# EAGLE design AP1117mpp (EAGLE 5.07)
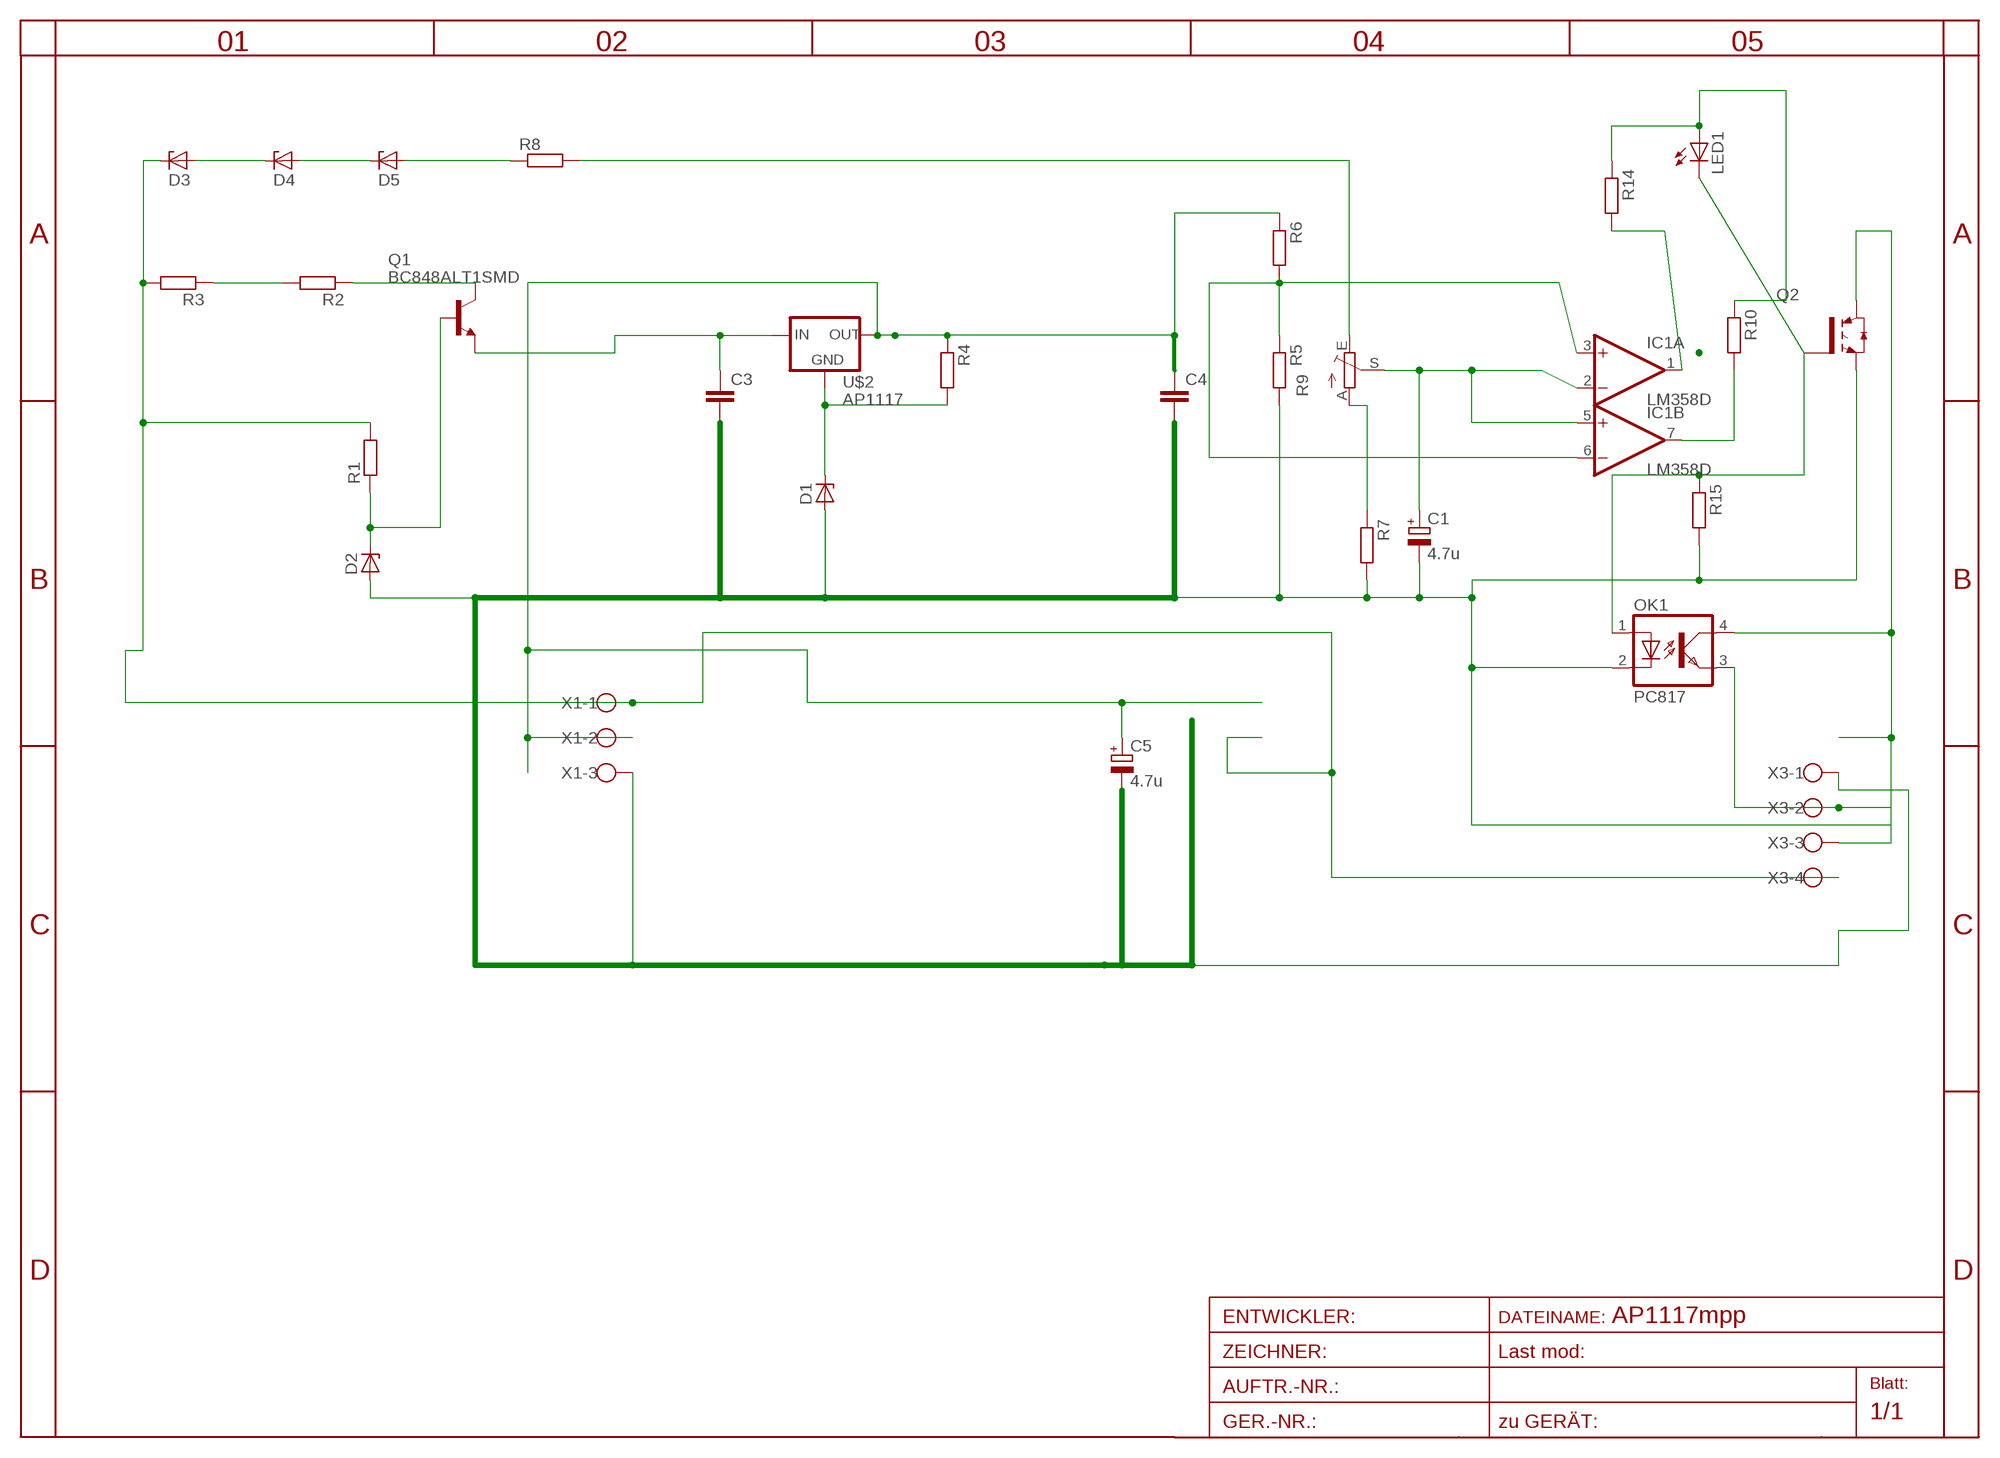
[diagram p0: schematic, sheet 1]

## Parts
C1  4.7u  CPOL-EUSANYO_SMD_C6  [SANYO-OSCON_SMD_C6]
C3  C-EUC1206  [C1206]
C4  C-EUC1206  [C1206]
C5  4.7u  CPOL-EUSANYO_SMD_C6  [SANYO-OSCON_SMD_C6]
D1  ZENER-DIODESOD80C  [SOD80C]
D2  ZENER-DIODESOD80C  [SOD80C]
D3  ZENER-DIODESOD80C  [SOD80C]
D4  ZENER-DIODESOD80C  [SOD80C]
D5  ZENER-DIODESOD80C  [SOD80C]
IC1  LM358D  [SO08]
LED1  LEDCHIPLED_1206  [CHIPLED_1206]
OK1  PC817  [DIL04]
Q1  BC848ALT1SMD  [SOT23]
Q2  IRG4BC15UD-S  [D2PACK]
R1  R-EU_R1206  [R1206]
R2  R-EU_R1206  [R1206]
R3  R-EU_R1206  [R1206]
R4  R-EU_R1206  [R1206]
R5  R-EU_R0805  [R0805]
R6  R-EU_R0805  [R0805]
R7  R-EU_R1206  [R1206]
R8  R-EU_R0805  [R0805]
R9  TRIM_EU-S64W  [S64W]
R10  R-EU_R1206  [R1206]
R14  R-EU_R0805  [R0805]
R15  R-EU_R0805  [R0805]
U$2  AP1117  [SOT223]
X1  W237-103  [W237-103]
X3  W237-4  [W237-4]

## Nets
A: R7.1 R9.A
E: R8.2 R9.E
IN: D3.C R1.2 R3.2 X1.1 X3.4
N$1: D1.C R4.2 U$2.1(GND)
N$2: C3.1 Q1.2(E) U$2.3(IN)
N$3: R2.2 R3.1
N$4: Q1.3(C) R2.1
N$5: D2.C Q1.1(B) R1.1
N$6: IC1.3(A:+IN) IC1.6(B:-IN) R5.1 R6.2
N$7: LED1.A R10.1 R14.1
N$8: IC1.7(B:OUT) R10.2
N$13: D5.A R8.1
N$14: D4.A D5.C
N$15: D3.A D4.C
N$17: IC1.1(A:OUT) R14.2
N$19: LED1.C OK1.1(A) Q2.1(G) R15.1
N$23: OK1.3(EMIT) X3.2
OUT-: OK1.4(COL) Q2.2(C) X3.3
S: C1.+ IC1.2(A:-IN) IC1.5(B:+IN) R9.S
V+: C4.1 C5.+ R4.1 R6.1 U$2.2(OUT) U$2.4(TAB) X1.2
V-: C1.- C3.2 C4.2 C5.- D1.A D2.A OK1.2(C) Q2.3(E) R5.2 R7.2 R15.2 X1.3 X3.1

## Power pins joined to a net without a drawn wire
V+: IC1.8(P:V+)
V-: IC1.4(P:V-)

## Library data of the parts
C1 C5 = rcl:CPOL-EU: POLARIZED CAPACITOR, European symbol
C3 C4 = rcl:C-EU: CAPACITOR, European symbol
D1-D5 = diode:ZENER-DIODE: Z-Diode
IC1 = linear:LM358: OP AMP also LM158; LM258; LM2904 Source: http://cache.national.com/ds/LM/LM158.pdf
LED1 = led:LED: LED
OK1 = optocoupler:PC817: SHARP OPTO COUPLER
Q1 = transistor-npn:BC848*: NPN Transistor
Q2 = transistor-power:IRG4BC15UD-: INSULATED GATE BIPOLAR TRANSISTOR WITH ULTRAFAST SOFT RECOVERY DIODE
R1-R8 R10 R14 R15 = rcl:R-EU_: RESISTOR, European symbol
R9 = pot:TRIM_EU-: POTENTIOMETER
U$2 = v-reg:AP1117
X1 = con-wago-500:W237-103: WAGO SCREW CLAMP
X3 = con-wago-500:W237-4: WAGO SCREW CLAMP

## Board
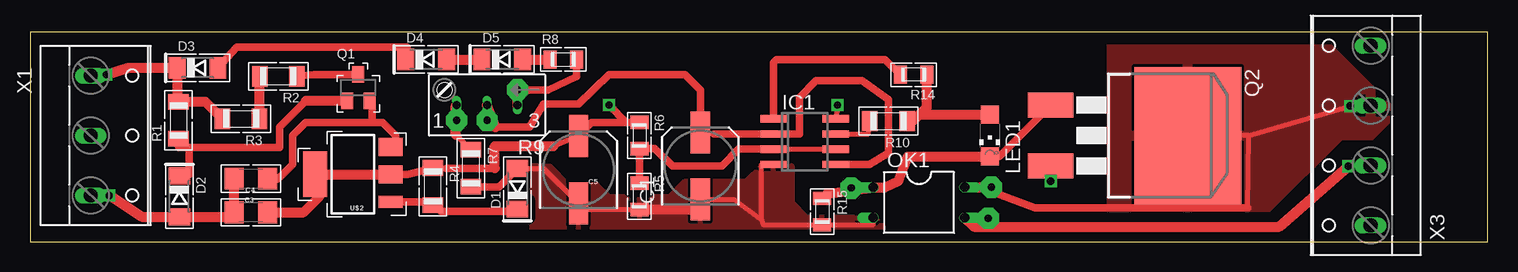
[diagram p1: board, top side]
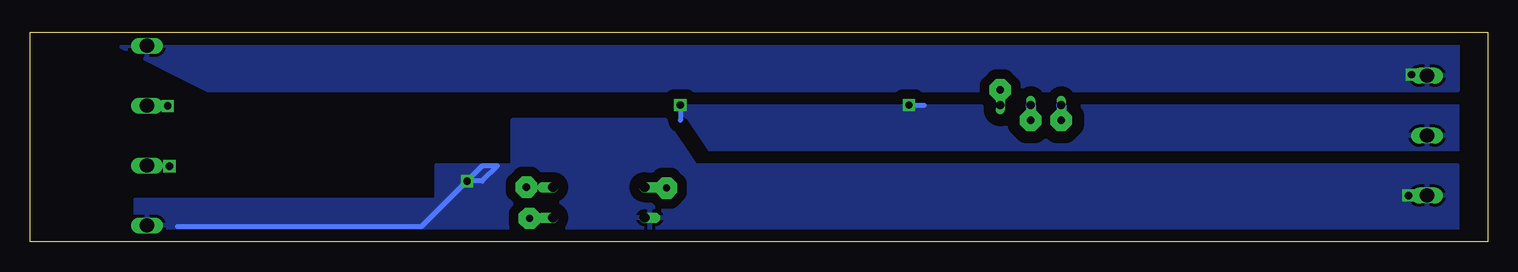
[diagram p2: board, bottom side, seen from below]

Size 121.52 x 17.5 mm. Coordinates in mm from the lower left corner, seen from the top.
Outline: 0,0 121.52,0 121.52,17.5 0,17.5 0,0
Copper layers (1*16): Top 0.035mm / dielectric 1.5mm / Bottom 0.035mm
Design rules "default": minimum track width 10mil, minimum drill 20mil, track to track 8mil, track to pad 8mil, pad to pad 8mil, via to via 8mil, smd to smd 8mil, copper to edge 40mil, drill to drill 8mil, minimum pad ring 1mil, minimum via ring 8mil, stop-mask expansion 4mil, vias tented up to drill 0mil, thermal gap 10mil

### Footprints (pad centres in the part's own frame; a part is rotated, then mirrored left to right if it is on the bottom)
SANYO-OSCON_SMD_C6 = smd 3.5 x 1.6: + 2.8,0; - -2.8,0
C1206 = smd 1.6 x 1.8: 1 -1.4,0; 2 1.4,0
SOD80C = smd 1.4 x 1.8: A 1.7,0; C -1.7,0
SO08 = smd 0.6 x 2.2: 1 -1.905,-2.6; 2 -0.635,-2.6; 3 0.635,-2.6; 4 1.905,-2.6; 5 1.905,2.6; 6 0.635,2.6; 7 -0.635,2.6; 8 -1.905,2.6
CHIPLED_1206 = smd 1.5 x 1.5: A 0,-1.75; C 0,1.75
DIL04 = drill 0.813 offset: 1 -1.27,-3.81; 2 1.27,-3.81; 3 1.27,3.81; 4 -1.27,3.81
SOT23 = smd 1 x 1.4: 1 -0.95,-1.1; 2 0.95,-1.1; 3 0,1.1
D2PACK = smd 2.083 x 3.81: 1 -2.54,-8.89; 3 2.54,-8.89 | smd 11.43 x 8.89: 2 0,2.54
R1206 = smd 1.3 x 1.7: 1 -1.55,0; 2 1.55,0
R0805 = smd 1.1 x 1.5: 1 -1.1,0; 2 1.1,0
S64W = drill 0.7 long: A 2.54,1.27; E -2.54,1.27; S 0,1.27
SOT223 = smd 1 x 2: 1 -2.3,-3.15 | smd 1.5 x 2: 2 0,-3.15; 3 2.3,-3.15 | smd 3.8 x 2: 4 0,3.15
W237-103 = drill 1.194 long: 1 -5,-1.29; 2 0,-1.29; 3 5,-1.29
W237-4 = drill 1.194 long: 1 -7.5,-1.27; 2 -2.5,-1.27; 3 2.5,-1.27; 4 7.5,-1.27

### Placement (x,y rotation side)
C1  55.88,6.35 90 top
C3  18.41,5.27 180 top
C4  18.41,2.48 180 top
C5  45.72,6.03 90 top
D1  40.64,4.45 90 top
D2  12.45,3.81 270 top
D3  13.97,14.54 0 top
D4  33.02,15.24 0 top
D5  39.37,15.24 0 top
IC1  64.58,8.38 270 top
LED1  80.01,8.89 180 top
OK1  74.1,3.3 270 top
Q1  27.37,12.89 0 top
Q2  93.98,8.89 270 top
R1  12.38,10.16 90 top
R2  20.7,13.84 180 top
R3  17.59,10.29 180 top
R4  33.59,4.64 270 top
R5  50.8,3.81 270 top
R6  50.8,8.89 270 top
R7  36.77,6.16 270 top
R8  44.45,15.24 0 top
R9  38.1,12.7 180 top
R10  71.56,10.1 180 top
R14  73.66,13.97 180 top
R15  66.04,2.54 270 top
U$2  26.92,5.65 90 top
X1  6.35,8.89 270 top
X3  110.49,8.89 90 top

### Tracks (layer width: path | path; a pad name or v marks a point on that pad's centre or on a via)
A  (via drill 0.6 pad 1.78)
  Top 0.406: R7.1 36.74,7.71 35.5,8.95 | 35.5,11.37 R9.A
  Top 0.813: 35.5,8.95 35.5,11.37
  Bottom 0.813: R9.A v35.56,10.16
E  (via drill 0.6 pad 1.78)
  Top 0.61: R8.2 45.55,13.8 43.18,12.7 v40.64,12.7
  Top 0.813: R9.E v40.64,12.7
IN  (via drill 0.6)
  Top 0.406: 12.27,11.82 R1.2
  Top 0.813: 12.27,11.82 D3.C 8.19,14.54 v6.35,13.97 | R1.2 14.62,11.71 R3.2
  Bottom 0.406: v6.35,13.97 5.14,13.97 X1.1
  pour Bottom (isolate 0.813): 114.3,16.51 2.54,16.51 2.54,12.7 106.68,12.7
N$1
  Top 0.406: 33.33,3.35 R4.2 33.74,3.09 34.29,2.54 | 40.43,2.54 D1.C
  Top 0.61: U$2.1 33.33,3.35 | 34.29,2.54 40.43,2.54
N$2
  Top 0.406: C3.1 20.7,5.27 | 28.39,9.97 28.51,10.1 | 28.51,12.17 Q1.2 | 30.48,8.36 U$2.3
  Top 0.61: 20.7,5.27 21.91,6.48 21.91,8.89 22.99,9.97 28.39,9.97 29.4,9.97 30.48,8.89 30.48,8.36 | 28.51,10.1 28.51,12.17
N$3
  Top 0.406: R2.2
  Top 0.813: R3.1 R2.2
N$4
  Top 0.61: R2.1 23.71,13.97 Q1.3
N$5
  Top 0.406: D2.C 13.27,5.64
  Top 0.61: 23.02,11.8 20.82,9.6 20.82,7.87 13.27,7.87 | 13.27,5.64 13.27,7.87 | 13.27,7.87 12.38,7.87 R1.1
  Top 0.813: 23.02,11.8 Q1.1
N$6
  Top 0.406: IC1.3 IC1.6
  Top 0.61: IC1.3 59.05,7.75 57.7,6.33 53.55,6.33 52.07,7.81 R6.2 R5.1
N$7
  Top 0.406: R10.1 73.66,10.16
  Top 0.813: 74.14,10.64 74.76,11.26 R14.1 | 73.66,10.16 74.14,10.64 | 74.14,10.64 LED1.A
N$8
  Top 0.406: IC1.7 69.89,9.02 R10.2
N$9  (via drill 0.6 pad 1.78)
  other vias: 68.45,4.51
N$10  (via drill 0.6 pad 1.78)
  other vias: 80.14,4.57
N$11  (via drill 0.6 pad 1.78)
  other vias: 79.88,1.97
N$13
  Top 0.813: D5.A R8.1
N$14
  Top 0.813: D4.A D5.C
N$15
  Top 0.406: 31.45,16.26 D4.C
  Top 0.61: D3.A 17.21,16.26 31.45,16.26
N$17
  Top 0.61: IC1.1 61.98,14.99 62.23,15.24 71.29,15.24 R14.2
N$19
  Top 0.406: R15.1 66.4,4 | LED1.C 80.8,7.14
  Top 0.61: 80.8,7.14 Q2.1
  Top 0.813: LED1.C 73.18,7.14 72.39,5.08 71.25,4.57 OK1.1 66.4,4
N$23  (via drill 0.6)
  Top 0.813: v109.9,6.33 104.14,1.27 78.68,1.27 OK1.3
  Bottom 0.406: v109.9,6.33 X3.2
OUT-  (via drill 0.6)
  Top 0.406: 101.6,8.89 97.79,8.89 96.52,10.16 95.25,8.89 95.25,7.62 Q2.2 | 101.54,2.86 101.6,8.89 | 101.6,8.89 v110.05,11.37
  Top 0.61: 79.25,4.57 83.76,2.86 101.54,2.86
  Top 0.813: OK1.4 79.25,4.57
  Bottom 0.406: X3.3 110.45,11.39 v110.05,11.37
  pour Top (isolate 0.813): 90.17,17.78 106.68,17.78 113.03,11.43 113.03,10.16 111.76,8.89 109.22,8.89 102.87,2.54 90.17,2.54
S  (via drill 0.6 pad 1.78)
  Top 0.406: C1.+ 57.02,9.02
  Top 0.61: 57.02,9.02 IC1.2 64.14,9.02 64.14,12.06 65.53,13.46 69.34,13.46 71.56,11.87 71.56,7.43 69.98,6.48 IC1.5 | C1.+ 55.88,12.7 54.61,13.97 48.26,13.97 45.72,11.5 42.8,11.5 41.66,9.59 38.8,9.59
  Top 0.813: 38.8,9.59 R9.S
  Bottom 0.813: R9.S v38.1,10.16
V+  (via drill 0.6)
  Top 0.406: 45.72,8.89 C5.+ 45.66,8.83 43.62,8 | 34.67,6.16 33.97,6.2 R4.1 | R6.1 49.7,9.99 | IC1.8 67.44,11.56 v67.31,11.43 | 24.13,3.81 24.13,5.29 U$2.4
  Top 0.61: U$2.2 31.47,5.65 R4.1 | R6.1 46.82,9.99 45.72,8.89 | 34.67,6.16 38.73,6.16 | 49.7,9.99 v48.26,11.43
  Top 0.813: U$2.4 U$2.2 | 43.62,8 38.73,8 38.73,6.16 | C4.1 22.8,2.48 24.13,3.81
  Bottom 0.406: v48.26,11.43 46.99,11.43 | v67.31,11.43 67.31,10.16
  pour Bottom (isolate 1.016, rank 4): 2.54,11.43 69.85,12.7 69.85,10.16 68.58,10.16 66.04,7.62 2.54,7.62
V-  (via drill 0.6)
  Top 0.406: OK1.2 70.3,1.44 R15.2 61.13,1.44 60.96,1.84 | 60.96,1.84 60.96,6.47 IC1.4 | 60.96,1.84 58.68,3.55 C1.- 55.04,2.71 | v85.09,5.08 Q2.3 | R5.2 46.24,2.71 C5.- 42.81,6.14 D1.A | 16.65,2.11 C4.2
  Top 0.61: R7.2 39.1,4.61 D1.A
  Top 0.813: R5.2 55.04,2.71 | C4.2 C3.2 | 16.65,2.11 D2.A 9.32,2.11 v6.6,3.87
  Bottom 0.406: v85.09,5.08 83.82,5.08 82.55,6.35 83.82,6.35 88.9,1.27 109.22,1.27 | v6.6,3.87 5.14,3.81 X1.3
  pour Bottom (isolate 0.813, rank 2): 2.54,0.32 2.54,6.35 66.04,6.35 68.58,10.16 81.28,10.16 81.28,6.35 87.63,6.35 87.63,3.49 112.71,3.49 112.71,0.64 16.51,0.64
  pour Top (isolate 0.61): 41.91,6.41 43.31,6.35 44.83,4.83 47.24,4.83 48.26,3.81 53.34,3.81 54.61,5.08 59.69,5.08 60.96,6.35 63.5,6.35 63.5,3.3 64.71,2.1 70.29,2.1 71.12,1.27 71.12,0 41.91,0 41.85,1.02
